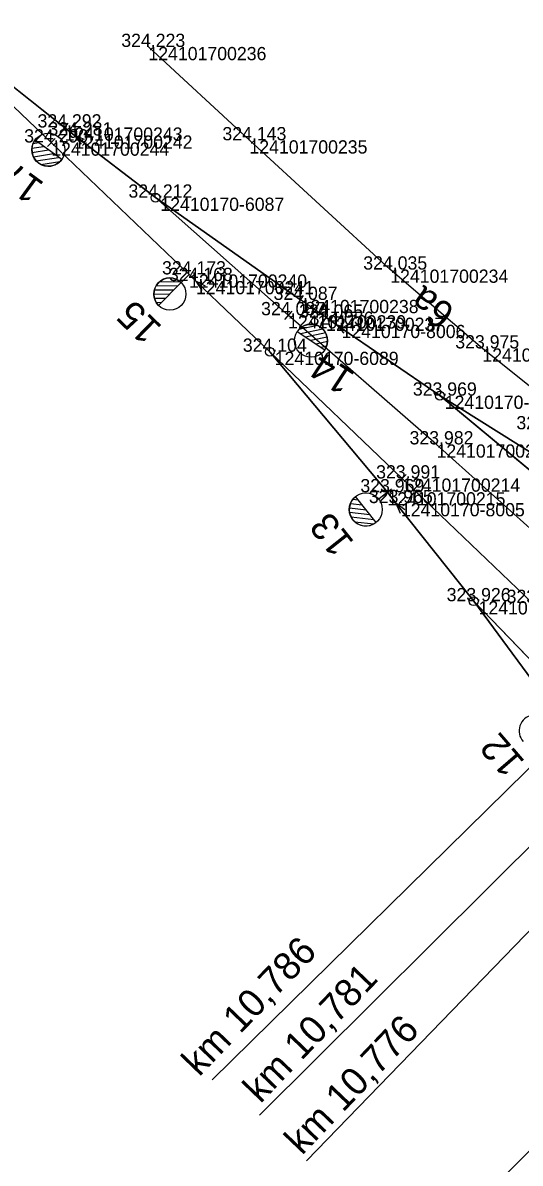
# Model space of a CAD drawing. Extents: x -616949 to -607976, y -1164436 to -1159224.
# Drawn here: x -616544.8 to -616499.7, y -1159491.5 to -1159388.1 of the extents above; entities that cross this region are included whole.
import ezdxf

# ---------------------------------------------------------------- set-up
doc = ezdxf.new("R2010")
doc.units = 0
for name, color, linetype in [('Vrstva 1', 7, 'Continuous'), ('Vrstva 2', 7, 'Continuous'), ('Vrstva 3', 7, 'Continuous'), ('Vrstva 5', 7, 'Continuous'), ('Vrstva 60', 7, 'Continuous'), ('Vrstva 61', 7, 'Continuous')]:
    doc.layers.add(name, color=color, linetype=linetype)

msp = doc.modelspace()

# ---------------------------------------------------------------- linework, layer by layer
at = {"layer": 'Vrstva 1'}
for points in [[(-616529.76, -1159410.94), (-616542.27, -1159398.98), (-616556.66, -1159385.22), (-616565.35, -1159376.92), (-616566.44, -1159375.88)], [(-616541.06, -1159397.62), (-616556.66, -1159385.22), (-616565.35, -1159376.92), (-616566.44, -1159375.88)], [(-616451.35, -1159450.67), (-616452.48, -1159450.16), (-616462.84, -1159445.51), (-616473.62, -1159438.84), (-616485.42, -1159431.04), (-616497.2, -1159422.39), (-616503.14, -1159417.65), (-616511.5, -1159410.5), (-616524.28, -1159398.78), (-616533.45, -1159390.32)], [(-616517.32, -1159414.86), (-616519.64, -1159413.25), (-616532.81, -1159403.98), (-616540.16, -1159398.34), (-616541.06, -1159397.62)], [(-616354.89, -1159571.54), (-616372.69, -1159554.54), (-616388.1, -1159539.8), (-616391.36, -1159536.67), (-616409.17, -1159519.63), (-616429.35, -1159500.31), (-616459.8, -1159471.15), (-616483.37, -1159448.57), (-616484.54, -1159447.45), (-616487.56, -1159444.55), (-616496.77, -1159435.79), (-616507.3, -1159426.35), (-616520.77, -1159414.64), (-616532.81, -1159403.98), (-616540.16, -1159398.34), (-616541.06, -1159397.62)], [(-616511.76, -1159430.69), (-616522.43, -1159417.95), (-616529.13, -1159411.54), (-616529.76, -1159410.94)], [(-616358.37, -1159574.75), (-616375.97, -1159557.93), (-616391.41, -1159543.18), (-616394.69, -1159540.05), (-616412.56, -1159522.96), (-616432.68, -1159503.75), (-616462.85, -1159474.92), (-616479.84, -1159458.67), (-616480.99, -1159457.57), (-616483.82, -1159454.87), (-616498.59, -1159440.73), (-616510.42, -1159429.44), (-616522.43, -1159417.95), (-616529.13, -1159411.54), (-616529.76, -1159410.94)], [(-616451.35, -1159450.67), (-616452.48, -1159450.16), (-616462.84, -1159445.51), (-616474.4, -1159440.32), (-616487.76, -1159433.64), (-616496.3, -1159428.63), (-616507, -1159421.93), (-616516.37, -1159415.51), (-616517.32, -1159414.86)], [(-616329.08, -1159589.6), (-616351, -1159568.64), (-616369.15, -1159551.29), (-616384.7, -1159536.43), (-616388.02, -1159533.25), (-616405.95, -1159516.12), (-616426.03, -1159496.92), (-616456.59, -1159467.68), (-616468.4, -1159456.4), (-616471.42, -1159453.51), (-616478.14, -1159447.08), (-616487.14, -1159438.68), (-616497.27, -1159429.99), (-616507, -1159421.93), (-616516.37, -1159415.51), (-616517.32, -1159414.86)], [(-616360.84, -1159578.72), (-616379.28, -1159561.06), (-616394.48, -1159546.5), (-616397.82, -1159543.33), (-616415.45, -1159526.43), (-616435.76, -1159507), (-616464.71, -1159479.28), (-616465.86, -1159478.17), (-616469.41, -1159474.76), (-616480.17, -1159464.46), (-616487.02, -1159457.86), (-616495.15, -1159449.67), (-616503.93, -1159440.57), (-616510.98, -1159431.67), (-616511.76, -1159430.69)], [(-616496.45, -1159450.7), (-616503.93, -1159440.57), (-616510.98, -1159431.67), (-616511.76, -1159430.69)]]:
    msp.add_lwpolyline(points, dxfattribs=at)
at = {"layer": 'Vrstva 2'}
for p, q in [((-616556.66, -1159385.22), (-616541.06, -1159397.62)), ((-616541.06, -1159397.62), (-616541.65, -1159398.43)), ((-616540.75, -1159397.23), (-616541.36, -1159398.02)), ((-616543.91, -1159399.07), (-616543.42, -1159398.99)), ((-616541.32, -1159400.53), (-616543.74, -1159398.76)), ((-616541.92, -1159398.62), (-616542.61, -1159399.34)), ((-616544.02, -1159399.49), (-616542.97, -1159399.33)), ((-616544.01, -1159399.89), (-616542.51, -1159399.66)), ((-616543.89, -1159400.28), (-616542.05, -1159399.99)), ((-616543.64, -1159400.65), (-616541.6, -1159400.33)), ((-616543.2, -1159400.98), (-616541.48, -1159400.71)), ((-616532.81, -1159403.98), (-616519.64, -1159413.25)), ((-616530.56, -1159411.6), (-616532.46, -1159411.63)), ((-616530.48, -1159411.67), (-616529.76, -1159410.94)), ((-616531.14, -1159412.36), (-616532.92, -1159412.38)), ((-616530.77, -1159411.98), (-616532.77, -1159412.01)), ((-616532.52, -1159413.77), (-616530.48, -1159411.67)), ((-616531.51, -1159412.74), (-616532.95, -1159412.76)), ((-616531.88, -1159413.12), (-616532.9, -1159413.13)), ((-616532.25, -1159413.5), (-616532.73, -1159413.51)), ((-616519.93, -1159413.66), (-616519.36, -1159412.84)), ((-616520.44, -1159414.27), (-616521.1, -1159415.02)), ((-616518.08, -1159415.58), (-616519.79, -1159415.93)), ((-616517.86, -1159415.7), (-616517.32, -1159414.86)), ((-616519.94, -1159416.13), (-616517.43, -1159417.77)), ((-616517.63, -1159415.89), (-616519.65, -1159416.32)), ((-616517.36, -1159416.25), (-616519.18, -1159416.63)), ((-616517.22, -1159416.63), (-616518.71, -1159416.94)), ((-616517.19, -1159417.03), (-616518.23, -1159417.25)), ((-616517.28, -1159417.46), (-616517.76, -1159417.56)), ((-616522.43, -1159417.95), (-616511.76, -1159430.69)), ((-616507, -1159421.93), (-616497.27, -1159429.99)), ((-616510.07, -1159429.08), (-616510.76, -1159429.8)), ((-616512.79, -1159433.42), (-616514.65, -1159431.07)), ((-616511.76, -1159430.69), (-616512.54, -1159431.31)), ((-616512.15, -1159431.01), (-616511.38, -1159430.37)), ((-616515.21, -1159432.09), (-616513.7, -1159432.27)), ((-616515.11, -1159431.7), (-616514.06, -1159431.82)), ((-616514.9, -1159431.32), (-616514.41, -1159431.38)), ((-616515.2, -1159432.5), (-616513.35, -1159432.71)), ((-616515.06, -1159432.92), (-616513, -1159433.15)), ((-616514.73, -1159433.36), (-616513, -1159433.56)), ((-616503.93, -1159440.57), (-616495.15, -1159449.67))]:
    msp.add_line(p, q, dxfattribs=at)
for points in [[(-616566.44, -1159375.88), (-616565.35, -1159376.92), (-616556.66, -1159385.22), (-616542.27, -1159398.98)], [(-616541.06, -1159397.62), (-616540.16, -1159398.34), (-616532.81, -1159403.98), (-616520.77, -1159414.64)], [(-616539.24, -1159398.72), (-616540.16, -1159398.34), (-616539.55, -1159399.13)], [(-616529.76, -1159410.94), (-616529.13, -1159411.54), (-616522.43, -1159417.95), (-616510.42, -1159429.44)], [(-616528.26, -1159412.02), (-616529.13, -1159411.54), (-616528.61, -1159412.4)], [(-616517.32, -1159414.86), (-616516.37, -1159415.51), (-616507, -1159421.93), (-616496.3, -1159428.63)], [(-616515.42, -1159415.84), (-616516.37, -1159415.51), (-616515.72, -1159416.27)], [(-616511.76, -1159430.69), (-616510.98, -1159431.67), (-616503.93, -1159440.57), (-616496.45, -1159450.7)], [(-616510.18, -1159432.27), (-616510.98, -1159431.67), (-616510.59, -1159432.59)]]:
    msp.add_lwpolyline(points, dxfattribs=at)
for centre, radius in [((-616542.53, -1159399.64), 1.5), ((-616532.81, -1159403.98), 0.4), ((-616531.5, -1159412.72), 1.46), ((-616518.69, -1159416.95), 1.5), ((-616522.43, -1159417.95), 0.4), ((-616507, -1159421.93), 0.4), ((-616513.72, -1159432.25), 1.5), ((-616503.93, -1159440.57), 0.4)]:
    msp.add_circle(centre, radius, dxfattribs=at)
for centre, radius, start, end in [((-616542.53, -1159399.64), 1.5, 143.8827, 323.8827), ((-616531.5, -1159412.72), 1.46, 45.809, 225.7699), ((-616518.69, -1159416.95), 1.5, 326.7716, 146.7716), ((-616513.72, -1159432.25), 1.5, 128.4196, 308.4196), ((-616498.35, -1159452.33), 1.46, 40.5205, 220.99)]:
    msp.add_arc(centre, radius, start, end, dxfattribs=at)
at = {"layer": 'Vrstva 3'}
for p, q in [((-616487.56, -1159444.55), (-616527.67, -1159483.96)), ((-616483.96, -1159448.01), (-616523.38, -1159487.17)), ((-616483.82, -1159454.87), (-616519.09, -1159491.31))]:
    msp.add_line(p, q, dxfattribs=at)
at = {"layer": 'Vrstva 5'}
msp.add_line((-616482.68, -1159473.97), (-616514.29, -1159505.99), dxfattribs=at)
at = {"layer": 'Vrstva 60'}
for p, q in [((-616533.45, -1159390.32), (-616533.45, -1159390.32)), ((-616541.06, -1159397.62), (-616541.06, -1159397.62)), ((-616542.27, -1159398.98), (-616542.27, -1159398.98)), ((-616540.16, -1159398.34), (-616540.16, -1159398.34)), ((-616524.28, -1159398.78), (-616524.28, -1159398.78)), ((-616532.81, -1159403.98), (-616532.81, -1159403.98)), ((-616511.5, -1159410.5), (-616511.5, -1159410.5)), ((-616529.76, -1159410.94), (-616529.76, -1159410.94)), ((-616529.13, -1159411.54), (-616529.13, -1159411.54)), ((-616519.64, -1159413.25), (-616519.64, -1159413.25)), ((-616520.77, -1159414.64), (-616520.77, -1159414.64)), ((-616517.32, -1159414.86), (-616517.32, -1159414.86)), ((-616516.37, -1159415.51), (-616516.37, -1159415.51)), ((-616503.14, -1159417.65), (-616503.14, -1159417.65)), ((-616522.43, -1159417.95), (-616522.43, -1159417.95)), ((-616507, -1159421.93), (-616507, -1159421.93)), ((-616507.3, -1159426.35), (-616507.3, -1159426.35)), ((-616510.42, -1159429.44), (-616510.42, -1159429.44)), ((-616511.76, -1159430.69), (-616511.76, -1159430.69)), ((-616510.98, -1159431.67), (-616510.98, -1159431.67)), ((-616503.93, -1159440.57), (-616503.93, -1159440.57))]:
    msp.add_line(p, q, dxfattribs=at)

# ---------------------------------------------------------------- texts
at = {"layer": 'Vrstva 1'}
msp.add_text('6a', height=2.5, rotation=143.7158, dxfattribs=at).set_placement((-616505.49, -1159414.06))
at = {"layer": 'Vrstva 2'}
for s, rotation, p in [('17', 143.8827, (-616542.8, -1159402.7)), ('15', 135.7899, (-616532.12, -1159415.7)), ('14', 146.7716, (-616514.56, -1159419.92)), ('13', 128.4196, (-616514.7, -1159435.23)), ('12', 130.7553, (-616499.2, -1159455.12))]:
    msp.add_text(s, height=2.5, rotation=rotation, dxfattribs=at).set_placement(p)
at = {"layer": 'Vrstva 3'}
for s, rotation, p in [('km 10,786', 46.1703, (-616528.85, -1159483.74)), ('km 10,781', 46.2519, (-616523.29, -1159486.17)), ('km 10,776', 46.3891, (-616519.51, -1159490.87))]:
    msp.add_text(s, height=2.5, rotation=rotation, dxfattribs=at).set_placement(p)
at = {"layer": 'Vrstva 60'}
for s, p in [('124101700236', (-616533.45, -1159391.52)), ('124101700243', (-616541.06, -1159398.82)), ('124101700244', (-616542.27, -1159400.18)), ('124101700242', (-616540.16, -1159399.54)), ('124101700235', (-616524.28, -1159399.98)), (' 12410170-6087', (-616532.81, -1159405.18)), ('124101700234', (-616511.5, -1159411.7)), ('124101700240', (-616529.76, -1159412.14)), ('124101700241', (-616529.13, -1159412.74)), ('124101700238', (-616519.64, -1159414.45)), ('124101700239', (-616520.77, -1159415.84)), ('124101700237', (-616517.32, -1159416.06)), (' 12410170-8006', (-616516.37, -1159416.71)), ('124101700233', (-616503.14, -1159418.85)), (' 12410170-6089', (-616522.43, -1159419.15)), (' 12410170-6086', (-616507, -1159423.13)), ('124101700216', (-616507.3, -1159427.55)), ('124101700214', (-616510.42, -1159430.64)), ('124101700215', (-616511.76, -1159431.89)), (' 12410170-8005', (-616510.98, -1159432.87)), (' 12410170-6090', (-616503.93, -1159441.77))]:
    msp.add_text(s, height=1.2, dxfattribs=at).set_placement(p)
at = {"layer": 'Vrstva 61'}
for s, p in [('324.223', (-616535.91, -1159390.32)), ('324.292', (-616543.51, -1159397.62)), ('324.281', (-616542.52, -1159398.34)), ('324.290', (-616544.72, -1159398.98)), ('324.143', (-616526.73, -1159398.78)), ('324.212', (-616535.26, -1159403.98)), ('324.035', (-616513.95, -1159410.5)), ('324.173', (-616532.21, -1159410.94)), ('324.168', (-616531.59, -1159411.54)), ('324.087', (-616522.09, -1159413.25)), ('324.087', (-616523.22, -1159414.64)), ('324.065', (-616519.77, -1159414.86)), ('324.056', (-616518.82, -1159415.51)), ('324.104', (-616524.88, -1159417.95)), ('323.975', (-616505.6, -1159417.65)), ('323.969', (-616509.45, -1159421.93)), ('323.733', (-616500.05, -1159424.98)), ('323.982', (-616509.75, -1159426.35)), ('323.991', (-616512.78, -1159429.44)), ('323.969', (-616514.21, -1159430.69)), ('323.965', (-616513.44, -1159431.67)), ('323.926', (-616506.38, -1159440.57)), ('323.901', (-616500.94, -1159440.73))]:
    msp.add_text(s, height=1.2, dxfattribs=at).set_placement(p)

doc.saveas('drawing.dxf')
